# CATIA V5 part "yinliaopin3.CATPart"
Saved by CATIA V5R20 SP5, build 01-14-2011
Part number: Part1
Material "Light Beige": density 7860 kg/m3, Young's modulus 2e+11 Pa, Poisson ratio 0.266
Bounding box of the stored display mesh (mm): x -25 to 25, y -25 to 25.2, z 0 to 110
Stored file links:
  E:\180122235\yinliaopin3.CATPart
  C:\Program Files\Dassault Systemes\B20\intel_a\startup\materials\Catalog.CATMaterial
  C:\Program Files\Dassault Systemes\B20\intel_a\startup\materials\sunset.jpg
  C:\Program Files\Dassault Systemes\B20\intel_a\startup\materials\yellow_env_512x512.jpg
  C:\Program Files\Dassault Systemes\B20\intel_a\startup\materials\birch.jpg
  C:\Program Files\Dassault Systemes\B20\intel_a\startup\materials\red_env_512x512.jpg
  C:\Program Files\Dassault Systemes\B20\intel_a\startup\materials\green_leather.jpg
  C:\Program Files\Dassault Systemes\B20\intel_a\startup\materials\brushed_metal1.jpg
  C:\Program Files\Dassault Systemes\B20\intel_a\startup\materials\green_env_512x512.jpg
  C:\Program Files\Dassault Systemes\B20\intel_a\startup\materials\black_env_512x512.jpg
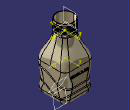
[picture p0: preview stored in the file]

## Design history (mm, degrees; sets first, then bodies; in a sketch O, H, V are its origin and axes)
Set1
  Sketch1 on face of Pad1 from Sketch3.L1, origin (25, 0, 0), H (0, 1, 0), V (0, 0, 1)
    spline S1 through (-40, 10) (-10, 20) (10, 10) (30, 20)
  Extrude1: Element1 Sketch1, Lim1 66, Lim2 66
  MultiSel1: CommonCtxFeats ({extract ExtractElem face of Fillet1}; {extract ExtractElem face of Pad1 from Sketch3.L1}; {extract ExtractElem face of Fillet1}; {extract ExtractElem face of Pad1 from Sketch3.L4}; {extract ExtractElem face of Fillet1}; {extract ExtractElem face of Pad1 from Sketch3.L3}; {extract ExtractElem face of Fillet1}; {extract ExtractElem face of Pad1 from Sketch3.L2})
  Sketch2 on face of Pad1 from Sketch3.L3, origin (-25, 0, 0), H (0, -1, 0), V (0, 0, 1)
    spline S1 through (-40, 20) (-10, 30) (10, 40) (30, 40)
  Extrude2: Element1 Sketch2, Lim1 66, Lim2 66
  MultiSel2: CommonCtxFeats ({extract ExtractElem face of Fillet1}; {extract ExtractElem face of Pad1 from Sketch3.L2}; {extract ExtractElem face of Fillet1}; {extract ExtractElem face of Pad1 from Sketch3.L1}; {extract ExtractElem face of Fillet1}; {extract ExtractElem face of Pad1 from Sketch3.L4}; {extract ExtractElem face of Fillet1}; {extract ExtractElem face of Pad1 from Sketch3.L3})
  Join1: Elements ({intersect ToIntersect1 {extract ExtractElem face of Fillet1}, ToIntersect2 Extrude2}; {intersect ToIntersect1 {extract ExtractElem face of Pad1 from Sketch3.L2}, ToIntersect2 Extrude2}; {intersect ToIntersect1 {extract ExtractElem face of Fillet1}, ToIntersect2 Extrude2}; {intersect ToIntersect1 {extract ExtractElem face of Pad1 from Sketch3.L1}, ToIntersect2 Extrude2}; {intersect ToIntersect1 {extract ExtractElem face of Fillet1}, ToIntersect2 Extrude2}; {intersect ToIntersect1 {extract ExtractElem face of Pad1 from Sketch3.L4}, ToIntersect2 Extrude2}; {intersect ToIntersect1 {extract ExtractElem face of Fillet1}, ToIntersect2 Extrude2}; {intersect ToIntersect1 {extract ExtractElem face of Pad1 from Sketch3.L3}, ToIntersect2 Extrude2})
  Join2: Elements ({intersect ToIntersect1 {extract ExtractElem face of Fillet1}, ToIntersect2 Extrude1}; {intersect ToIntersect1 {extract ExtractElem face of Pad1 from Sketch3.L1}, ToIntersect2 Extrude1}; {intersect ToIntersect1 {extract ExtractElem face of Fillet1}, ToIntersect2 Extrude1}; {intersect ToIntersect1 {extract ExtractElem face of Pad1 from Sketch3.L4}, ToIntersect2 Extrude1}; {intersect ToIntersect1 {extract ExtractElem face of Fillet1}, ToIntersect2 Extrude1}; {intersect ToIntersect1 {extract ExtractElem face of Pad1 from Sketch3.L3}, ToIntersect2 Extrude1}; {intersect ToIntersect1 {extract ExtractElem face of Fillet1}, ToIntersect2 Extrude1}; {intersect ToIntersect1 {extract ExtractElem face of Pad1 from Sketch3.L2}, ToIntersect2 Extrude1})
  Plane1: type Normal, Curve Join1, RefPoint vertex [face of MultiSel2 | face of MultiSel2]
  Circle1: type CtrRad, Start 0, End 180, Center vertex [face of MultiSel2 | face of MultiSel2], Support Plane1, Radius 1, FirstDirection (1, 0, 0)
  Plane2: type Normal, Curve Join2, RefPoint vertex [face of MultiSel1 | face of MultiSel1]
  Circle2: type CtrRad, Start 0, End 180, Center vertex [face of MultiSel1 | face of MultiSel1], Support Plane2, Radius 1, FirstDirection (1, 0, 0)
Body1 (main body), material "Light Beige"
  Set2
    Sketch3 on xy-plane, origin (0, 0, 0), H (1, 0, 0), V (0, 1, 0)
      line L1 (25, 25) -> (25, -25)
      line L2 (25, -25) -> (-25, -25)
      line L3 (-25, -25) -> (-25, 25)
      line L4 (-25, 25) -> (25, 25)
      distance L2 L4 = 50
      distance L1 L3 = 50
      vertical: L1 V, L3 V
      horizontal: L2 H, L4 H
      equidistance: L1 L3 O, L2 L4 O
  Pad1: profile Sketch3, direction (0, 0, 1), length 50
  Fillet1: on edge [face of Pad1 from Sketch3.L2 | face of Pad1 from Sketch3.L3]; edge [face of Pad1 from Sketch3.L4 | face of Pad1 from Sketch3.L1]; edge [face of Pad1 from Sketch3.L3 | face of Pad1 from Sketch3.L4]; edge [face of Pad1 from Sketch3.L1 | face of Pad1 from Sketch3.L2]
  Fillet2: on edge [start face of Pad1 | face of Pad1 from Sketch3.L4]
  Plane3: type Offset, RefPlane end face of Pad1, Offset 40, reversed
  Sketch4 on Plane3, origin (0, 0, 90), H (1, 0, 0), V (0, -1, 0)
    circle A1 centre (0, 0) radius 15
    radius A1 = 15
  Pad2: profile Sketch4, direction (0, 0, -1), length -20
  Sketch5 on end face of Pad1, origin (0, 0, 50), H (1, 0, 0), V (0, 1, 0)
    point P1 (25, 0)
    distance V P1 = 25
    coincidence: P1 H
  Sketch6 on start face of Pad2, origin (0, 0, 90), H (1, 0, 0), V (0, -1, 0)
    point P1 (15, 0)
    distance P1 V = 15
    coincidence: P1 H
  Loft1: solid, Sections ({boundary Boundary {extract ExtractElem end face of Pad1}}; {boundary Boundary {extract ExtractElem start face of Pad2}}), StartFace end face of Pad1, EndFace start face of Pad2
  Slot1: profile Circle1, centre curve Join1
  Slot2: profile Circle2, centre curve Join2
  Shell1: ExtOffset 0, Face end face of Pad2, IntOffset 1
  Sketch7 on {extract ExtractElem start face of Pad2}, origin (0, 0, 90), H (1, 0, 0), V (0, 1, 0)
    point P1 (15, 0)
    distance P1 V = 15
    coincidence: P1 H
  Plane4: type Offset, RefPlane {extract ExtractElem start face of Pad2}, Offset 2
  Sketch8 on Plane4, origin (0, 0, 92), H (1, 0, 0), V (0, 1, 0)
    point P1 (15, 0)
    distance P1 V = 15
    coincidence: P1 H
  Helix1: Direction Z axis, RefPoint Sketch8, Pitch 2, Height 15, TaperAngle 0
  Point1: type OnCurve, Support Helix1, RefPoint vertex of Helix1, Length -3.889
  Line1: type PtDir, RefPoint vertex of Helix1, Direction (1, 0, 0), Start 0, End 7
  Connect1: Curve1 Helix1, Point1 Point1, Tension1 1, Curve2 Line1, Point2 vertex of Line1, Tension2 1
  Line2: type PtDir, RefPoint Sketch8, Direction (1, 0, 0), Start 0, End -7
  Point2: type OnCurve, Support Connect1, Length 5.227
  Connect2: Curve1 Line2, Point1 vertex of Line2, Tension1 1, Curve2 Connect1, Point2 Point2, Tension2 1
  Plane5: type Normal, Curve Connect2, RefPoint vertex of Connect1
  Sketch9 on Plane5, origin (-8, 0, 0), H (0, 1, 0), V (0, 0, 1)
    circle A1 centre (0, 107.0454) radius 0.5
    point P1 (0, 107.0454)
    coincidence: P1 V
  Rib1: profile Sketch9, centre curve Connect2
  Body2
    Sketch10 on face of Pad1 from Sketch3.L4, origin (0, 25, 0), H (-1, 0, 0), V (0, 0, 1)
      polyline C1
      polyline C2
      polyline C3
      polyline C4
      polyline C5
      polyline C6
      polyline C7
      polyline C8
      polyline C9
      polyline C10
      polyline C11
    Sketch11 on {extract ExtractElem start face of Pad2}, origin (0, 0, 90), H (1, 0, 0), V (0, 1, 0)
      circle A1 centre (0, 0) radius 14
      radius A1 = 14
    Pad3: profile Sketch11, direction (0, 0, 1), length 20
  Remove1: tool Body2
  Pad4: profile Sketch10, direction (0, 1, 0), length 0.2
